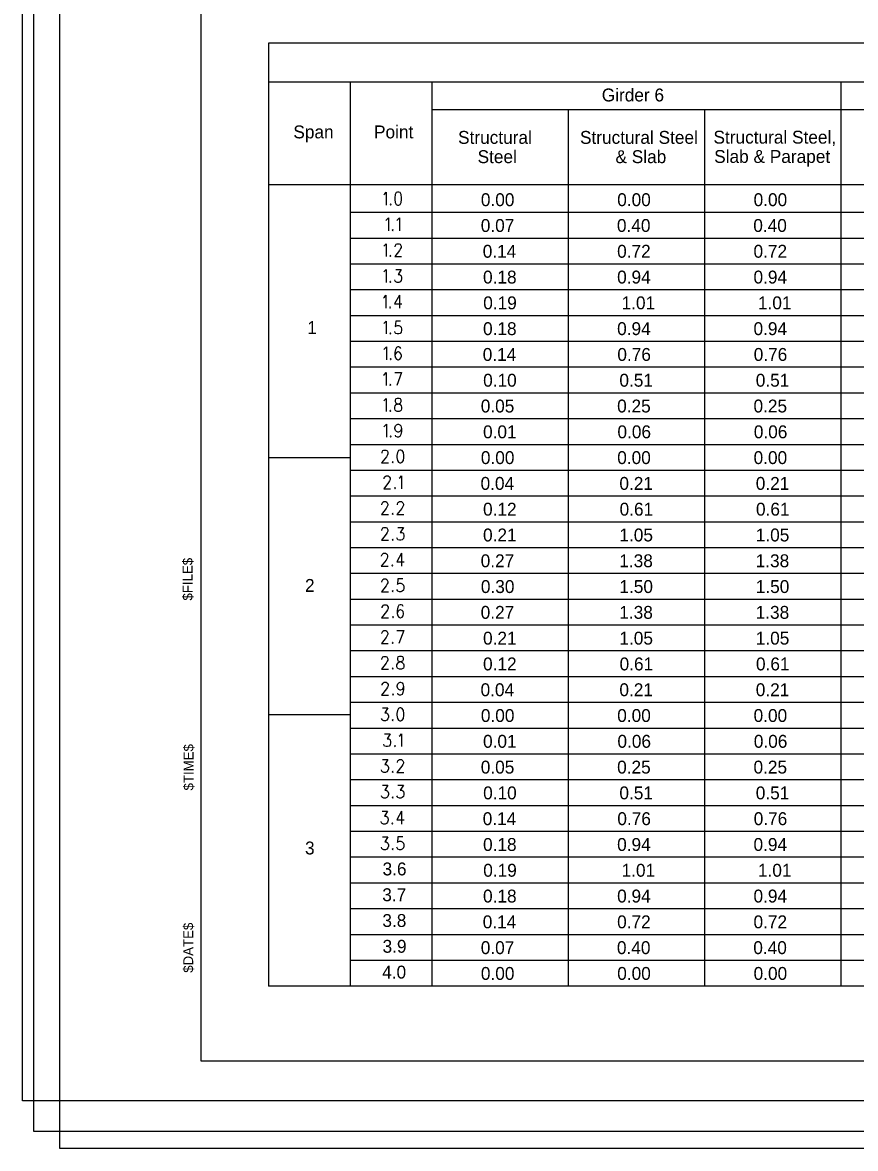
# Model space of a CAD drawing. Extents: x 208.5 to 250.5, y 328.7 to 350.7.
# Drawn here: x 208.55 to 216.62, y 328.74 to 339.65 of the extents above; entities that cross this region are included whole.
import ezdxf

# ---------------------------------------------------------------- set-up
doc = ezdxf.new("R2010")
doc.units = 0
for name, color, linetype in [('border', 7, 'Continuous'), ('Border 2660-Hwy18 - Level 62', 7, 'Continuous'), ('Border 2660-Hwy18 - Level 63', 7, 'Continuous'), ('Level 62 PDF', 7, 'Continuous'), ('Steel', 7, 'Continuous'), ('Text', 7, 'Continuous')]:
    doc.layers.add(name, color=color, linetype=linetype)

msp = doc.modelspace()

# ---------------------------------------------------------------- linework, layer by layer
at = {"layer": 'border'}
for p, q in [((210.28, 329.584), (210.28, 350.129)), ((242.291, 329.584), (210.28, 329.584))]:
    msp.add_line(p, q, dxfattribs=at)
at = {"layer": 'Border 2660-Hwy18 - Level 62'}
msp.add_lwpolyline([(208.659, 350.715), (242.778, 350.715), (242.778, 328.905), (208.659, 328.905)], close=True, dxfattribs=at)
at = {"layer": 'Border 2660-Hwy18 - Level 63'}
msp.add_lwpolyline([(208.548, 350.572), (242.548, 350.572), (242.548, 329.202), (208.548, 329.202)], close=True, dxfattribs=at)
at = {"layer": 'Level 62 PDF'}
msp.add_lwpolyline([(208.909, 350.548), (243.028, 350.548), (243.028, 328.739), (208.909, 328.739)], close=True, dxfattribs=at)
at = {"layer": 'Steel'}
for p, q in [((210.932, 339.452), (210.932, 330.311)), ((228.381, 339.452), (210.932, 339.452)), ((228.381, 339.075), (210.932, 339.075)), ((211.725, 339.075), (211.725, 330.311)), ((212.517, 339.075), (212.517, 330.311)), ((212.517, 339.075), (212.517, 330.311)), ((216.483, 339.075), (216.483, 330.311)), ((228.381, 338.806), (212.517, 338.806)), ((213.839, 338.806), (213.839, 330.311)), ((215.161, 338.806), (215.161, 330.311)), ((228.381, 338.08), (210.932, 338.08)), ((228.381, 337.811), (211.725, 337.811)), ((228.381, 337.561), (211.725, 337.561)), ((228.381, 337.311), (211.725, 337.311)), ((228.381, 337.061), (211.725, 337.061)), ((228.381, 336.811), (211.725, 336.811)), ((228.381, 336.561), (211.725, 336.561)), ((228.381, 336.311), (211.725, 336.311)), ((228.381, 336.061), (211.725, 336.061)), ((228.381, 335.811), (211.725, 335.811)), ((228.381, 335.561), (211.725, 335.561)), ((211.725, 335.433), (210.932, 335.433)), ((228.381, 335.311), (211.725, 335.311)), ((228.381, 335.061), (211.725, 335.061)), ((228.381, 334.811), (211.725, 334.811)), ((228.381, 334.561), (211.725, 334.561)), ((228.381, 334.311), (211.725, 334.311)), ((228.381, 334.061), (211.725, 334.061)), ((228.381, 333.811), (211.725, 333.811)), ((228.381, 333.561), (211.725, 333.561)), ((228.381, 333.311), (211.725, 333.311)), ((228.381, 333.061), (211.725, 333.061)), ((211.725, 332.943), (210.932, 332.943)), ((228.381, 332.811), (211.725, 332.811)), ((228.381, 332.561), (211.725, 332.561)), ((228.381, 332.311), (211.725, 332.311)), ((228.381, 332.061), (211.725, 332.061)), ((228.381, 331.811), (211.725, 331.811)), ((228.381, 331.561), (211.725, 331.561)), ((228.381, 331.311), (211.725, 331.311)), ((228.381, 331.061), (211.725, 331.061)), ((228.381, 330.811), (211.725, 330.811)), ((228.381, 330.561), (211.725, 330.561)), ((228.381, 330.311), (210.932, 330.311))]:
    msp.add_line(p, q, dxfattribs=at)
at = {"layer": 'Text'}
for p, q in [((212.202, 337.009), (212.202, 336.884)), ((212.157, 336.259), (212.224, 336.259)), ((212.224, 336.259), (212.176, 336.134)), ((212.223, 334.509), (212.223, 334.384)), ((212.178, 333.759), (212.245, 333.759)), ((212.245, 333.759), (212.197, 333.634)), ((212.223, 332.009), (212.223, 331.884))]:
    msp.add_line(p, q, dxfattribs=at)
for points in [[(212.051, 337.985), (212.06, 337.992), (212.074, 338.009), (212.074, 337.884)], [(212.185, 338.009), (212.171, 338.004), (212.161, 337.985), (212.157, 337.955), (212.157, 337.938), (212.161, 337.908), (212.171, 337.89), (212.185, 337.884), (212.195, 337.884), (212.209, 337.89), (212.219, 337.908), (212.224, 337.938), (212.224, 337.955), (212.219, 337.985), (212.209, 338.004), (212.195, 338.009), (212.185, 338.009)], [(212.116, 337.896), (212.111, 337.89), (212.116, 337.884), (212.121, 337.89), (212.116, 337.896)], [(212.071, 337.735), (212.081, 337.742), (212.095, 337.759), (212.095, 337.634)], [(212.178, 337.735), (212.188, 337.742), (212.202, 337.759), (212.202, 337.634)], [(212.137, 337.646), (212.132, 337.64), (212.137, 337.634), (212.141, 337.64), (212.137, 337.646)], [(212.05, 337.485), (212.059, 337.492), (212.073, 337.509), (212.073, 337.384)], [(212.161, 337.479), (212.161, 337.485), (212.166, 337.497), (212.171, 337.504), (212.18, 337.509), (212.199, 337.509), (212.209, 337.504), (212.213, 337.497), (212.219, 337.485), (212.219, 337.473), (212.213, 337.461), (212.204, 337.443), (212.157, 337.384), (212.224, 337.384)], [(212.115, 337.396), (212.11, 337.39), (212.115, 337.384), (212.12, 337.39), (212.115, 337.396)], [(212.05, 337.235), (212.059, 337.242), (212.073, 337.259), (212.073, 337.134)], [(212.166, 337.259), (212.219, 337.259), (212.19, 337.211), (212.204, 337.211), (212.213, 337.205), (212.219, 337.199), (212.224, 337.182), (212.224, 337.17), (212.219, 337.152), (212.209, 337.14), (212.195, 337.134), (212.18, 337.134), (212.166, 337.14), (212.161, 337.146), (212.157, 337.158)], [(212.115, 337.146), (212.11, 337.14), (212.115, 337.134), (212.12, 337.14), (212.115, 337.146)], [(212.047, 336.985), (212.057, 336.992), (212.071, 337.009), (212.071, 336.884)], [(212.202, 337.009), (212.154, 336.926), (212.226, 336.926)], [(212.113, 336.896), (212.108, 336.89), (212.113, 336.884), (212.117, 336.89), (212.113, 336.896)], [(212.05, 336.735), (212.059, 336.742), (212.073, 336.759), (212.073, 336.634)], [(212.213, 336.759), (212.166, 336.759), (212.161, 336.705), (212.166, 336.711), (212.18, 336.717), (212.195, 336.717), (212.209, 336.711), (212.219, 336.699), (212.224, 336.682), (212.224, 336.67), (212.219, 336.652), (212.209, 336.64), (212.195, 336.634), (212.18, 336.634), (212.166, 336.64), (212.161, 336.646), (212.157, 336.658)], [(212.115, 336.646), (212.11, 336.64), (212.115, 336.634), (212.12, 336.64), (212.115, 336.646)], [(212.052, 336.485), (212.062, 336.492), (212.076, 336.509), (212.076, 336.384)], [(212.217, 336.492), (212.211, 336.504), (212.197, 336.509), (212.187, 336.509), (212.173, 336.504), (212.164, 336.485), (212.159, 336.455), (212.159, 336.426), (212.164, 336.402), (212.173, 336.39), (212.187, 336.384), (212.192, 336.384), (212.206, 336.39), (212.217, 336.402), (212.221, 336.42), (212.221, 336.426), (212.217, 336.443), (212.206, 336.455), (212.192, 336.461), (212.187, 336.461), (212.173, 336.455), (212.164, 336.443), (212.159, 336.426)], [(212.117, 336.396), (212.113, 336.39), (212.117, 336.384), (212.122, 336.39), (212.117, 336.396)], [(212.049, 336.235), (212.058, 336.242), (212.073, 336.259), (212.073, 336.134)], [(212.114, 336.146), (212.11, 336.14), (212.114, 336.134), (212.119, 336.14), (212.114, 336.146)], [(212.05, 335.985), (212.059, 335.992), (212.073, 336.009), (212.073, 335.884)], [(212.18, 336.009), (212.166, 336.004), (212.161, 335.992), (212.161, 335.979), (212.166, 335.967), (212.176, 335.961), (212.195, 335.955), (212.209, 335.949), (212.219, 335.938), (212.224, 335.926), (212.224, 335.908), (212.219, 335.896), (212.213, 335.89), (212.199, 335.884), (212.18, 335.884), (212.166, 335.89), (212.161, 335.896), (212.157, 335.908), (212.157, 335.926), (212.161, 335.938), (212.171, 335.949), (212.185, 335.955), (212.204, 335.961), (212.213, 335.967), (212.219, 335.979), (212.219, 335.992), (212.213, 336.004), (212.199, 336.009), (212.18, 336.009)], [(212.115, 335.896), (212.11, 335.89), (212.115, 335.884), (212.12, 335.89), (212.115, 335.896)], [(212.052, 335.735), (212.062, 335.742), (212.076, 335.759), (212.076, 335.634)], [(212.221, 335.717), (212.216, 335.699), (212.206, 335.688), (212.192, 335.682), (212.187, 335.682), (212.173, 335.688), (212.164, 335.699), (212.159, 335.717), (212.159, 335.723), (212.164, 335.742), (212.173, 335.754), (212.187, 335.759), (212.192, 335.759), (212.206, 335.754), (212.216, 335.742), (212.221, 335.717), (212.221, 335.688), (212.216, 335.658), (212.206, 335.64), (212.192, 335.634), (212.183, 335.634), (212.169, 335.64), (212.164, 335.652)], [(212.117, 335.646), (212.113, 335.64), (212.117, 335.634), (212.122, 335.64), (212.117, 335.646)], [(212.034, 335.479), (212.034, 335.485), (212.038, 335.497), (212.043, 335.504), (212.052, 335.509), (212.071, 335.509), (212.081, 335.504), (212.086, 335.497), (212.091, 335.485), (212.091, 335.473), (212.086, 335.461), (212.076, 335.443), (212.029, 335.384), (212.096, 335.384)], [(212.207, 335.509), (212.193, 335.504), (212.183, 335.485), (212.178, 335.455), (212.178, 335.438), (212.183, 335.408), (212.193, 335.39), (212.207, 335.384), (212.216, 335.384), (212.23, 335.39), (212.241, 335.408), (212.245, 335.438), (212.245, 335.455), (212.241, 335.485), (212.23, 335.504), (212.216, 335.509), (212.207, 335.509)], [(212.138, 335.396), (212.133, 335.39), (212.138, 335.384), (212.142, 335.39), (212.138, 335.396)], [(212.054, 335.229), (212.054, 335.235), (212.059, 335.247), (212.064, 335.254), (212.073, 335.259), (212.092, 335.259), (212.102, 335.254), (212.106, 335.247), (212.112, 335.235), (212.112, 335.223), (212.106, 335.211), (212.097, 335.193), (212.05, 335.134), (212.117, 335.134)], [(212.2, 335.235), (212.21, 335.242), (212.224, 335.259), (212.224, 335.134)], [(212.158, 335.146), (212.154, 335.14), (212.158, 335.134), (212.163, 335.14), (212.158, 335.146)], [(212.033, 334.979), (212.033, 334.985), (212.038, 334.997), (212.042, 335.004), (212.052, 335.009), (212.071, 335.009), (212.08, 335.004), (212.085, 334.997), (212.09, 334.985), (212.09, 334.973), (212.085, 334.961), (212.075, 334.943), (212.028, 334.884), (212.095, 334.884)], [(212.183, 334.979), (212.183, 334.985), (212.188, 334.997), (212.193, 335.004), (212.202, 335.009), (212.221, 335.009), (212.23, 335.004), (212.235, 334.997), (212.241, 334.985), (212.241, 334.973), (212.235, 334.961), (212.226, 334.943), (212.178, 334.884), (212.245, 334.884)], [(212.137, 334.896), (212.132, 334.89), (212.137, 334.884), (212.141, 334.89), (212.137, 334.896)], [(212.033, 334.729), (212.033, 334.735), (212.038, 334.747), (212.042, 334.754), (212.052, 334.759), (212.071, 334.759), (212.08, 334.754), (212.085, 334.747), (212.09, 334.735), (212.09, 334.723), (212.085, 334.711), (212.075, 334.693), (212.028, 334.634), (212.095, 334.634)], [(212.188, 334.759), (212.241, 334.759), (212.211, 334.711), (212.226, 334.711), (212.235, 334.705), (212.241, 334.699), (212.245, 334.682), (212.245, 334.67), (212.241, 334.652), (212.23, 334.64), (212.216, 334.634), (212.202, 334.634), (212.188, 334.64), (212.183, 334.646), (212.178, 334.658)], [(212.137, 334.646), (212.132, 334.64), (212.137, 334.634), (212.141, 334.64), (212.137, 334.646)], [(212.03, 334.479), (212.03, 334.485), (212.035, 334.497), (212.04, 334.504), (212.049, 334.509), (212.068, 334.509), (212.078, 334.504), (212.082, 334.497), (212.088, 334.485), (212.088, 334.473), (212.082, 334.461), (212.073, 334.443), (212.026, 334.384), (212.093, 334.384)], [(212.223, 334.509), (212.176, 334.426), (212.248, 334.426)], [(212.134, 334.396), (212.13, 334.39), (212.134, 334.384), (212.139, 334.39), (212.134, 334.396)], [(212.033, 334.229), (212.033, 334.235), (212.038, 334.247), (212.042, 334.254), (212.052, 334.259), (212.071, 334.259), (212.08, 334.254), (212.085, 334.247), (212.09, 334.235), (212.09, 334.223), (212.085, 334.211), (212.075, 334.193), (212.028, 334.134), (212.095, 334.134)], [(212.235, 334.259), (212.188, 334.259), (212.183, 334.205), (212.188, 334.211), (212.202, 334.217), (212.216, 334.217), (212.23, 334.211), (212.241, 334.199), (212.245, 334.182), (212.245, 334.17), (212.241, 334.152), (212.23, 334.14), (212.216, 334.134), (212.202, 334.134), (212.188, 334.14), (212.183, 334.146), (212.178, 334.158)], [(212.137, 334.146), (212.132, 334.14), (212.137, 334.134), (212.141, 334.14), (212.137, 334.146)], [(212.035, 333.979), (212.035, 333.985), (212.04, 333.997), (212.045, 334.004), (212.054, 334.009), (212.073, 334.009), (212.082, 334.004), (212.087, 333.997), (212.093, 333.985), (212.093, 333.973), (212.087, 333.961), (212.078, 333.943), (212.03, 333.884), (212.097, 333.884)], [(212.238, 333.992), (212.233, 334.004), (212.219, 334.009), (212.209, 334.009), (212.195, 334.004), (212.186, 333.985), (212.181, 333.955), (212.181, 333.926), (212.186, 333.902), (212.195, 333.89), (212.209, 333.884), (212.214, 333.884), (212.228, 333.89), (212.238, 333.902), (212.243, 333.92), (212.243, 333.926), (212.238, 333.943), (212.228, 333.955), (212.214, 333.961), (212.209, 333.961), (212.195, 333.955), (212.186, 333.943), (212.181, 333.926)], [(212.139, 333.896), (212.134, 333.89), (212.139, 333.884), (212.144, 333.89), (212.139, 333.896)], [(212.032, 333.729), (212.032, 333.735), (212.037, 333.747), (212.041, 333.754), (212.051, 333.759), (212.07, 333.759), (212.079, 333.754), (212.084, 333.747), (212.089, 333.735), (212.089, 333.723), (212.084, 333.711), (212.075, 333.693), (212.027, 333.634), (212.094, 333.634)], [(212.136, 333.646), (212.131, 333.64), (212.136, 333.634), (212.141, 333.64), (212.136, 333.646)], [(212.033, 333.479), (212.033, 333.485), (212.038, 333.497), (212.042, 333.504), (212.052, 333.509), (212.071, 333.509), (212.08, 333.504), (212.085, 333.497), (212.09, 333.485), (212.09, 333.473), (212.085, 333.461), (212.075, 333.443), (212.028, 333.384), (212.095, 333.384)], [(212.202, 333.509), (212.188, 333.504), (212.183, 333.492), (212.183, 333.479), (212.188, 333.467), (212.197, 333.461), (212.216, 333.455), (212.23, 333.449), (212.241, 333.438), (212.245, 333.426), (212.245, 333.408), (212.241, 333.396), (212.235, 333.39), (212.221, 333.384), (212.202, 333.384), (212.188, 333.39), (212.183, 333.396), (212.178, 333.408), (212.178, 333.426), (212.183, 333.438), (212.193, 333.449), (212.207, 333.455), (212.226, 333.461), (212.235, 333.467), (212.241, 333.479), (212.241, 333.492), (212.235, 333.504), (212.221, 333.509), (212.202, 333.509)], [(212.137, 333.396), (212.132, 333.39), (212.137, 333.384), (212.141, 333.39), (212.137, 333.396)], [(212.035, 333.229), (212.035, 333.235), (212.04, 333.247), (212.045, 333.254), (212.054, 333.259), (212.073, 333.259), (212.082, 333.254), (212.087, 333.247), (212.093, 333.235), (212.093, 333.223), (212.087, 333.211), (212.078, 333.194), (212.03, 333.134), (212.097, 333.134)], [(212.243, 333.217), (212.237, 333.199), (212.228, 333.188), (212.214, 333.182), (212.209, 333.182), (212.195, 333.188), (212.186, 333.199), (212.181, 333.217), (212.181, 333.223), (212.186, 333.242), (212.195, 333.254), (212.209, 333.259), (212.214, 333.259), (212.228, 333.254), (212.237, 333.242), (212.243, 333.217), (212.243, 333.188), (212.237, 333.158), (212.228, 333.14), (212.214, 333.134), (212.204, 333.134), (212.19, 333.14), (212.186, 333.152)], [(212.139, 333.146), (212.134, 333.14), (212.139, 333.134), (212.144, 333.14), (212.139, 333.146)], [(212.038, 333.009), (212.091, 333.009), (212.062, 332.961), (212.076, 332.961), (212.086, 332.955), (212.091, 332.949), (212.096, 332.932), (212.096, 332.92), (212.091, 332.902), (212.081, 332.89), (212.067, 332.884), (212.052, 332.884), (212.038, 332.89), (212.034, 332.896), (212.029, 332.908)], [(212.207, 333.009), (212.193, 333.004), (212.183, 332.985), (212.178, 332.955), (212.178, 332.938), (212.183, 332.908), (212.193, 332.89), (212.207, 332.884), (212.216, 332.884), (212.23, 332.89), (212.241, 332.908), (212.245, 332.938), (212.245, 332.955), (212.241, 332.985), (212.23, 333.004), (212.216, 333.009), (212.207, 333.009)], [(212.138, 332.896), (212.133, 332.89), (212.138, 332.884), (212.142, 332.89), (212.138, 332.896)], [(212.059, 332.759), (212.112, 332.759), (212.083, 332.711), (212.097, 332.711), (212.106, 332.705), (212.112, 332.699), (212.117, 332.682), (212.117, 332.67), (212.112, 332.652), (212.102, 332.64), (212.088, 332.634), (212.073, 332.634), (212.059, 332.64), (212.054, 332.646), (212.05, 332.658)], [(212.2, 332.735), (212.21, 332.742), (212.224, 332.759), (212.224, 332.634)], [(212.158, 332.646), (212.154, 332.64), (212.158, 332.634), (212.163, 332.64), (212.158, 332.646)], [(212.038, 332.509), (212.09, 332.509), (212.061, 332.461), (212.075, 332.461), (212.085, 332.455), (212.09, 332.449), (212.095, 332.432), (212.095, 332.42), (212.09, 332.402), (212.08, 332.39), (212.066, 332.384), (212.052, 332.384), (212.038, 332.39), (212.033, 332.396), (212.028, 332.408)], [(212.183, 332.479), (212.183, 332.485), (212.188, 332.497), (212.193, 332.504), (212.202, 332.509), (212.221, 332.509), (212.23, 332.504), (212.235, 332.497), (212.241, 332.485), (212.241, 332.473), (212.235, 332.461), (212.226, 332.444), (212.178, 332.384), (212.245, 332.384)], [(212.137, 332.396), (212.132, 332.39), (212.137, 332.384), (212.141, 332.39), (212.137, 332.396)], [(212.038, 332.259), (212.09, 332.259), (212.061, 332.211), (212.075, 332.211), (212.085, 332.205), (212.09, 332.199), (212.095, 332.182), (212.095, 332.17), (212.09, 332.152), (212.08, 332.14), (212.066, 332.134), (212.052, 332.134), (212.038, 332.14), (212.033, 332.146), (212.028, 332.158)], [(212.188, 332.259), (212.241, 332.259), (212.211, 332.211), (212.226, 332.211), (212.235, 332.205), (212.241, 332.199), (212.245, 332.182), (212.245, 332.17), (212.241, 332.152), (212.23, 332.14), (212.216, 332.134), (212.202, 332.134), (212.188, 332.14), (212.183, 332.146), (212.178, 332.158)], [(212.137, 332.146), (212.132, 332.14), (212.137, 332.134), (212.141, 332.14), (212.137, 332.146)], [(212.035, 332.009), (212.088, 332.009), (212.059, 331.961), (212.073, 331.961), (212.082, 331.955), (212.088, 331.949), (212.093, 331.932), (212.093, 331.92), (212.088, 331.902), (212.078, 331.89), (212.063, 331.884), (212.049, 331.884), (212.035, 331.89), (212.03, 331.896), (212.026, 331.908)], [(212.223, 332.009), (212.176, 331.926), (212.248, 331.926)], [(212.134, 331.896), (212.13, 331.89), (212.134, 331.884), (212.139, 331.89), (212.134, 331.896)], [(212.038, 331.759), (212.09, 331.759), (212.061, 331.711), (212.075, 331.711), (212.085, 331.705), (212.09, 331.699), (212.095, 331.682), (212.095, 331.67), (212.09, 331.652), (212.08, 331.64), (212.066, 331.634), (212.052, 331.634), (212.038, 331.64), (212.033, 331.646), (212.028, 331.658)], [(212.235, 331.759), (212.188, 331.759), (212.183, 331.705), (212.188, 331.711), (212.202, 331.717), (212.216, 331.717), (212.23, 331.711), (212.241, 331.699), (212.245, 331.682), (212.245, 331.67), (212.241, 331.652), (212.23, 331.64), (212.216, 331.634), (212.202, 331.634), (212.188, 331.64), (212.183, 331.646), (212.178, 331.658)], [(212.137, 331.646), (212.132, 331.64), (212.137, 331.634), (212.141, 331.64), (212.137, 331.646)]]:
    msp.add_lwpolyline(points, dxfattribs=at)

# ---------------------------------------------------------------- texts
at = {"layer": 'border'}
for s, p in [('$FILE$', (210.197, 334.05)), ('$TIME$', (210.206, 332.209)), ('$DATE$', (210.203, 330.442))]:
    msp.add_text(s, height=0.096, rotation=89.9999, dxfattribs=at).set_placement(p)
at = {"layer": 'Text'}
for s, p in [('Girder 6', (214.164, 338.888)), ('Span', (211.174, 338.53)), ('Point', (211.956, 338.53)), ('Structural', (212.771, 338.477)), ('Structural Steel', (213.953, 338.477)), ('Structural Steel,', (215.247, 338.479)), ('Steel', (212.96, 338.29)), ('& Slab', (214.297, 338.29)), ('Slab & Parapet', (215.254, 338.292)), ('0.00', (212.992, 337.873)), ('0.00', (214.314, 337.873)), ('0.00', (215.636, 337.873)), ('0.07', (212.991, 337.623)), ('0.40', (214.311, 337.623)), ('0.40', (215.633, 337.623)), ('0.14', (213.01, 337.373)), ('0.72', (214.313, 337.373)), ('0.72', (215.635, 337.373)), ('0.18', (213.013, 337.123)), ('0.94', (214.313, 337.123)), ('0.94', (215.635, 337.123)), ('0.19', (213.015, 336.873)), ('1.01', (214.356, 336.873)), ('1.01', (215.678, 336.873)), ('1', (211.309, 336.634)), ('0.18', (213.013, 336.623)), ('0.94', (214.313, 336.623)), ('0.94', (215.635, 336.623)), ('0.14', (213.01, 336.373)), ('0.76', (214.315, 336.373)), ('0.76', (215.637, 336.373)), ('0.10', (213.014, 336.123)), ('0.51', (214.335, 336.123)), ('0.51', (215.657, 336.123)), ('0.05', (212.991, 335.873)), ('0.25', (214.313, 335.873)), ('0.25', (215.635, 335.873)), ('0.01', (213.013, 335.623)), ('0.06', (214.316, 335.623)), ('0.06', (215.638, 335.623)), ('0.00', (212.992, 335.373)), ('0.00', (214.314, 335.373)), ('0.00', (215.636, 335.373)), ('0.04', (212.989, 335.123)), ('0.21', (214.335, 335.123)), ('0.21', (215.657, 335.123)), ('0.12', (213.013, 334.873)), ('0.61', (214.337, 334.873)), ('0.61', (215.659, 334.873)), ('0.21', (213.013, 334.623)), ('1.05', (214.335, 334.623)), ('1.05', (215.657, 334.623)), ('0.27', (212.99, 334.373)), ('1.38', (214.334, 334.373)), ('1.38', (215.656, 334.373)), ('2', (211.287, 334.134)), ('0.30', (212.992, 334.123)), ('1.50', (214.335, 334.123)), ('1.50', (215.657, 334.123)), ('0.27', (212.99, 333.873)), ('1.38', (214.334, 333.873)), ('1.38', (215.656, 333.873)), ('0.21', (213.013, 333.623)), ('1.05', (214.335, 333.623)), ('1.05', (215.657, 333.623)), ('0.12', (213.013, 333.373)), ('0.61', (214.337, 333.373)), ('0.61', (215.659, 333.373)), ('0.04', (212.989, 333.123)), ('0.21', (214.335, 333.123)), ('0.21', (215.657, 333.123)), ('0.00', (212.992, 332.873)), ('0.00', (214.314, 332.873)), ('0.00', (215.636, 332.873)), ('0.01', (213.013, 332.623)), ('0.06', (214.316, 332.623)), ('0.06', (215.638, 332.623)), ('0.05', (212.991, 332.373)), ('0.25', (214.313, 332.373)), ('0.25', (215.635, 332.373)), ('0.10', (213.014, 332.123)), ('0.51', (214.335, 332.123)), ('0.51', (215.657, 332.123)), ('0.14', (213.01, 331.873)), ('0.76', (214.315, 331.873)), ('0.76', (215.637, 331.873)), ('3', (211.287, 331.589)), ('0.18', (213.013, 331.623)), ('0.94', (214.313, 331.623)), ('0.94', (215.635, 331.623)), ('3.6', (212.039, 331.386)), ('0.19', (213.015, 331.373)), ('1.01', (214.356, 331.373)), ('1.01', (215.678, 331.373)), ('3.7', (212.036, 331.136)), ('0.18', (213.013, 331.123)), ('0.94', (214.313, 331.123)), ('0.94', (215.635, 331.123)), ('3.8', (212.037, 330.886)), ('0.14', (213.01, 330.873)), ('0.72', (214.313, 330.873)), ('0.72', (215.635, 330.873)), ('3.9', (212.039, 330.636)), ('0.07', (212.991, 330.623)), ('0.40', (214.311, 330.623)), ('0.40', (215.633, 330.623)), ('4.0', (212.035, 330.386)), ('0.00', (212.992, 330.373)), ('0.00', (214.314, 330.373)), ('0.00', (215.636, 330.373))]:
    msp.add_text(s, height=0.125, dxfattribs=at).set_placement(p)

doc.saveas('drawing.dxf')
